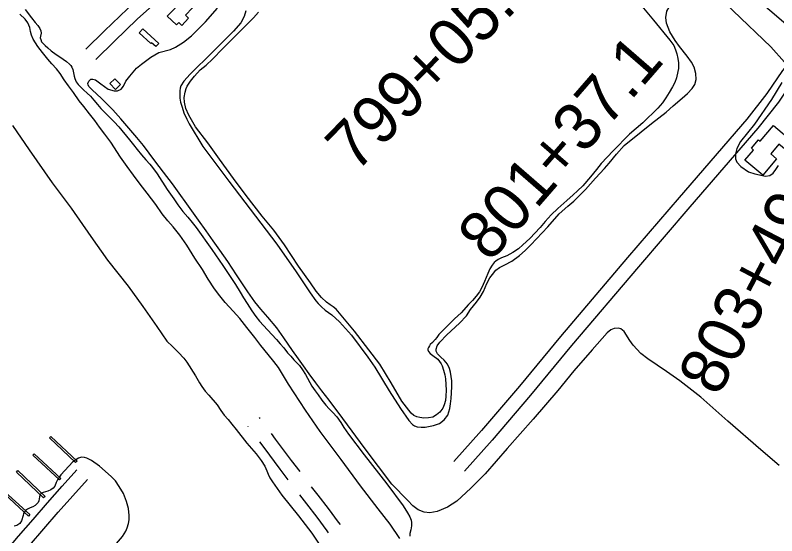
# Model space of a CAD drawing. Extents: x 3823584 to 3861785, y 301729 to 327625.
# Drawn here: x 3834881 to 3836481, y 323407 to 324501 of the extents above; entities that cross this region are included whole.
import ezdxf

# ---------------------------------------------------------------- set-up
doc = ezdxf.new("R2010")
doc.units = 0
for name, color, linetype in [('V-BLDG-OTLN', 7, 'Continuous'), ('V-CHAN-DOCK', 7, 'Continuous'), ('V-RIVR-EDGE', 7, 'Continuous'), ('V-ROAD-CNTR', 7, 'Continuous'), ('V-SITE-VEGE', 7, 'Continuous'), ('V-SURV-IDEN', 7, 'Continuous'), ('V-TOPO-SHOR', 7, 'Continuous')]:
    doc.layers.add(name, color=color, linetype=linetype)

msp = doc.modelspace()

# ---------------------------------------------------------------- linework, layer by layer
at = {"layer": 'V-BLDG-OTLN'}
for points in [[(3835200.4, 324499.1), (3835234.1, 324534.2), (3835242.5, 324526.1), (3835251.8, 324535.8), (3835256.1, 324531.6), (3835262.3, 324538), (3835268.6, 324532), (3835238.9, 324501.1), (3835245.4, 324494.8), (3835230.8, 324479.7), (3835224.6, 324485.7), (3835219.7, 324480.6)], [(3835148.9, 324472.4), (3835182.6, 324441.8), (3835176.4, 324435), (3835167.3, 324443.3), (3835166, 324441.9), (3835141.4, 324464.2)], [(3835090.5, 324367.6), (3835102.5, 324355.3), (3835092, 324345.2), (3835080.1, 324357.5)], [(3836474.5, 324269.6), (3836516.1, 324234.2), (3836501.5, 324217.1), (3836486, 324230.3), (3836468.6, 324209.8), (3836481.2, 324199.1), (3836451.9, 324164.8), (3836414.6, 324196.6), (3836432.7, 324217.7), (3836428, 324221.7), (3836442.9, 324239.2), (3836446.2, 324236.3)]]:
    msp.add_lwpolyline(points, close=True, dxfattribs=at)
at = {"layer": 'V-CHAN-DOCK'}
for points in [[(3835008, 323560.5), (3834952.9, 323612.4), (3834956.1, 323615.8), (3835011.2, 323563.9)], [(3834974.3, 323524.5), (3834918.1, 323576.3), (3834920.7, 323579.2), (3834976.9, 323527.4)], [(3834940.7, 323486.3), (3834883.6, 323540.7), (3834886.8, 323544), (3834943.9, 323489.6)], [(3834908.7, 323448.3), (3834848.4, 323503.1), (3834851.1, 323506.1), (3834911.4, 323451.2)]]:
    msp.add_lwpolyline(points, close=True, dxfattribs=at)
at = {"layer": 'V-RIVR-EDGE'}
msp.add_spline([(3836304.4, 325474.2), (3836346.4, 325438.3), (3836389.4, 325406.1), (3836417.6, 325385.4), (3836442.7, 325366.7), (3836470.2, 325340.9), (3836497.8, 325313.9), (3836554.9, 325258.4), (3836598.5, 325215.9), (3836636.4, 325181.1), (3836681.3, 325139.8), (3836737.1, 325093.4), (3836790.9, 325041.2), (3836840.3, 324993.5), (3836889.1, 324947.1), (3836934.6, 324907.1), (3836980.8, 324871), (3837015.5, 324849.1), (3837040.5, 324829.1), (3837085.4, 324787.2), (3837143.8, 324734.3), (3837181.6, 324700.8), (3837223.3, 324659.6), (3837272.1, 324619.6), (3837314.4, 324579.6), (3837346.4, 324546.8), (3837364.4, 324527.4), (3837395.8, 324500.4), (3837442, 324462.3), (3837492.7, 324423), (3837554.3, 324372.7), (3837573.6, 324361.1), (3837583.2, 324359.1), (3837596.7, 324352.6), (3837621.1, 324337.8), (3837648, 324319.7), (3837677.5, 324292), (3837718.6, 324249.5), (3837753.8, 324214.7), (3837781.4, 324188.9), (3837800, 324179.8), (3837820, 324170.8), (3837850.7, 324134.1), (3837874.4, 324110.2), (3837909.1, 324073.5), (3837941.8, 324040.6), (3837989.9, 323991.7), (3838022.6, 323960.7), (3838034.1, 323947.8), (3838046.3, 323933.7), (3838066.8, 323916.3), (3838089.9, 323892.4), (3838140.6, 323849.2), (3838186.1, 323811.2), (3838215.7, 323785.4), (3838265.7, 323736.4), (3838297.1, 323707.4), (3838336.9, 323671.9), (3838360, 323645.5), (3838385.6, 323627.5), (3838404.2, 323615.8), (3838421.6, 323601.7), (3838441.4, 323582.3), (3838460, 323567.5), (3838468.4, 323563.6), (3838484.4, 323555.2), (3838548.6, 323496.6), (3838595.4, 323464.3), (3838650, 323422.4), (3838701.3, 323379.8), (3838749.4, 323345.6), (3838798.2, 323317.9), (3838856.6, 323274.6), (3838933, 323221.7), (3838989.5, 323184.3), (3839037.6, 323150.1), (3839068.4, 323134.6), (3839093.4, 323105), (3839110.7, 323086.9), (3839122.9, 323081.1), (3839143.5, 323065.6), (3839172.3, 323044.4), (3839191, 323032.7), (3839216, 323016), (3839242.3, 323006.3), (3839316.8, 322969.4), (3839341.8, 322955.9), (3839371.4, 322944.2), (3839391.3, 322935.8), (3839417.6, 322920.3), (3839461.3, 322894.5), (3839483.7, 322873.2), (3839520.3, 322851.3), (3839555.6, 322828.7), (3839599.9, 322806.7), (3839718.7, 322751.1), (3839768.1, 322726.6), (3839807.9, 322705.9), (3839836.9, 322696.2), (3839865.1, 322680.7), (3839887.6, 322667.8), (3839924.2, 322652.3), (3839969.8, 322630.3), (3840004.4, 322612.2), (3840037.8, 322597.4), (3840085.4, 322579.9), (3840108.5, 322565.7), (3840121.9, 322548.9), (3840123.2, 322539.9), (3840122.5, 322533.5), (3840118, 322521.3), (3840112.8, 322514.2), (3840095.5, 322509.1), (3840089.7, 322509.2), (3840085.2, 322504.7), (3840084.5, 322498.2), (3840085.8, 322491.8), (3840130.7, 322467.3), (3840169.9, 322448.5), (3840197.5, 322439.5), (3840209.1, 322437.5), (3840231.6, 322441.3), (3840246.4, 322449), (3840266.3, 322458.6), (3840273.4, 322466.3), (3840278.6, 322471.4), (3840288.9, 322480.4), (3840296, 322484.9), (3840301.8, 322484.8), (3840308.2, 322484.8), (3840320.4, 322479), (3840324.9, 322470), (3840326.8, 322461.6), (3840338.3, 322450), (3840344.7, 322444.9), (3840366.6, 322437.7), (3840385.8, 322428.1), (3840421.8, 322409.3), (3840466.1, 322385.4), (3840492.4, 322368.7), (3840506.5, 322357), (3840533.5, 322340.3), (3840559.2, 322331.2), (3840587.4, 322322.1), (3840611.8, 322311.8), (3840642, 322296.3), (3840678.6, 322276.3), (3840712.6, 322255.6), (3840733.2, 322242.1), (3840784.5, 322210.4), (3840835.9, 322183.3), (3840892.4, 322153.6), (3840923.9, 322139.4), (3840950.8, 322127.1), (3840989.3, 322100), (3841017.6, 322082.6), (3841061.2, 322062.5), (3841092.7, 322044.4), (3841151.1, 322005.1), (3841210.8, 321964.4), (3841240.3, 321939.3), (3841300, 321894.8), (3841335.9, 321862.6), (3841374.4, 321823.9), (3841411.6, 321789.7), (3841444.9, 321758.1), (3841469.9, 321736.2), (3841482.1, 321724), (3841496.2, 321704.7), (3841509.1, 321694.3), (3841523.2, 321687.2), (3841573.9, 321660.7), (3841624, 321631.7), (3841667.6, 321606.5), (3841696.5, 321593.6), (3841738.3, 321575.5), (3841787.1, 321556.7), (3841816, 321552.1), (3841851.3, 321545), (3841886.7, 321533.3), (3841930.3, 321511.4), (3841950.2, 321498.5), (3841977.2, 321483), (3841998.4, 321476.5), (3842053, 321463.5), (3842082.5, 321456.3), (3842109.5, 321444.7), (3842146.1, 321427.3), (3842196.2, 321402.1), (3842241.1, 321374.9), (3842288.6, 321345.3), (3842321.4, 321327.2), (3842366.9, 321295.6), (3842395.2, 321280.1), (3842429.2, 321264.6), (3842452.4, 321258.7), (3842471, 321249.7)], degree=3, dxfattribs=at)
at = {"layer": 'V-ROAD-CNTR'}
for p, q in [((3835395.6, 323653.6), (3835394.5, 323655.1)), ((3835370.8, 323636.7), (3835370.5, 323637.1))]:
    msp.add_line(p, q, dxfattribs=at)
for points in [[(3835362.2, 325460.9), (3835509.5, 325334.3), (3835871.8, 325022.8), (3836108.4, 324817.6), (3836414, 324556.9), (3836839.8, 324193.7), (3837163.7, 323918.8), (3837445, 323669.4), (3837836.5, 323328.4), (3838069.6, 323134.9), (3838125.4, 323086.8), (3838256, 322989.5), (3838600, 322735.4), (3839019.3, 322425.4), (3839565.5, 322022.9), (3840024.9, 321675.2), (3840474.9, 321350), (3840728.4, 321161.3)], [(3835756.2, 325122.1), (3835727.3, 325085.6), (3835693.5, 325050.5), (3835646, 325004.3), (3835566.9, 324926.9), (3835457.9, 324826.8), (3835364.5, 324741.6), (3835267.6, 324652.3), (3835175, 324567.3), (3835116.6, 324514.7), (3835068.4, 324468.3), (3835029.1, 324429.5)], [(3835779, 325102.6), (3835749.9, 325065.8), (3835714.7, 325029.3), (3835667, 324982.8), (3835587.5, 324905.1), (3835478.1, 324804.6), (3835384.7, 324719.5), (3835287.9, 324630.2), (3835195.1, 324545.1), (3835137, 324492.7), (3835089.4, 324446.8), (3835050.1, 324408.2)], [(3836543.5, 324446.4), (3836522.3, 324418), (3836493.8, 324384.9), (3836460.6, 324336.3), (3836418.7, 324282.8), (3836276.1, 324118.1), (3836167.8, 323991.5), (3836027.2, 323826), (3835940.7, 323721.6), (3835861, 323627.8), (3835803, 323563)], [(3836540.6, 324442.5), (3836522.3, 324418), (3836493.8, 324384.9), (3836460.6, 324336.3), (3836418.7, 324282.8), (3836276.1, 324118.1), (3836167.8, 323991.5), (3836027.2, 323826), (3835940.7, 323721.6), (3835861, 323627.8), (3835803, 323563)], [(3836566.4, 324426.9), (3836545.8, 324399.2), (3836517.6, 324366.5), (3836484.8, 324318.6), (3836441.9, 324263.7), (3836298.9, 324098.5), (3836190.6, 323972.1), (3836050.2, 323806.7), (3835963.7, 323702.3), (3835883.6, 323608), (3835825.4, 323542.9)], [(3836564.7, 324424.6), (3836545.8, 324399.2), (3836517.6, 324366.5), (3836484.8, 324318.6), (3836441.9, 324263.7), (3836298.9, 324098.5), (3836190.6, 323972.1), (3836050.2, 323806.7), (3835963.7, 323702.3), (3835883.6, 323608), (3835825.4, 323542.9)], [(3835479.6, 323541.6), (3835461.8, 323565.1), (3835428.1, 323610.1), (3835419.5, 323621.6)], [(3835454.8, 323524.6), (3835437.9, 323547.1), (3835404.1, 323592.1), (3835394.8, 323604.6)], [(3834858.5, 323371.1), (3834888.1, 323405.9), (3834918.4, 323441.1), (3834948.9, 323476), (3834979.5, 323510.8), (3835010.4, 323545.4)], [(3834880.5, 323350.7), (3834910.9, 323386.4), (3834941.1, 323421.4), (3834971.4, 323456.3), (3835002, 323490.9), (3835032.8, 323525.4)], [(3835564.3, 323430.2), (3835560.6, 323435.2), (3835539.1, 323463.8), (3835517.4, 323492.2), (3835503.8, 323509.8)], [(3835539.6, 323413.2), (3835536.6, 323417.3), (3835515.2, 323445.7), (3835493.6, 323473.9), (3835479, 323492.8)]]:
    msp.add_lwpolyline(points, dxfattribs=at)
at = {"layer": 'V-SITE-VEGE'}
for points in [[(3836311.9, 324365.7), (3836311, 324378.7), (3836307.8, 324391.6), (3836302.5, 324402.2), (3836293.1, 324415), (3836276.8, 324435.2), (3836267.9, 324448.1), (3836256.9, 324466.1), (3836249.8, 324484.4), (3836248.2, 324496.6), (3836250.6, 324509.9), (3836259.9, 324526.5), (3836278.7, 324543.9), (3836295.7, 324552.5), (3836305.7, 324554.5), (3836319.8, 324556.1), (3836336.2, 324555.2), (3836350.5, 324549.6), (3836389.5, 324510.4), (3836468.9, 324434.4), (3836497.6, 324402.1)], [(3836172.7, 323817.3), (3836161, 323836.1), (3836154, 323841.9), (3836147.8, 323843.4), (3836139.5, 323842.7), (3836132.6, 323839.7), (3836125.1, 323833.7), (3836093.2, 323797.5), (3836055.2, 323753.2), (3836021.3, 323712), (3835969.3, 323652.2), (3835914.5, 323590.4), (3835868.4, 323537.2), (3835838.2, 323506.6), (3835809.4, 323479.8), (3835789.5, 323466.9), (3835768, 323458.1), (3835752, 323455), (3835740.4, 323456.3), (3835728.1, 323461.4), (3835716.7, 323469.4), (3835706.3, 323480.9), (3835672.5, 323515.4), (3835616.3, 323589.7), (3835569.4, 323653.5), (3835540.8, 323691.8), (3835525.4, 323711.6), (3835513, 323728.3), (3835498.7, 323747.1), (3835486.8, 323764.2), (3835476, 323778.9), (3835463.6, 323796.2), (3835445.6, 323822.6), (3835430.5, 323844.1), (3835412.2, 323866), (3835397.3, 323883.1), (3835384.7, 323898.7), (3835369.8, 323919.4), (3835346.2, 323955.5), (3835328.1, 323983.2), (3835311.2, 324007.3), (3835297, 324026.8), (3835282.6, 324048.1), (3835265.9, 324070.3), (3835241.5, 324104.4), (3835225.4, 324127.1), (3835211.3, 324146.5), (3835192.8, 324170.9), (3835174.5, 324194.9), (3835150.4, 324227.2), (3835136.9, 324244.2), (3835115.8, 324268.3), (3835103, 324283.2), (3835086, 324301.9), (3835062.3, 324326.3), (3835043, 324344), (3835035.5, 324351.2), (3835034.2, 324354.7), (3835033.8, 324357.6), (3835035.7, 324362.7), (3835040.1, 324366.4), (3835044.3, 324366.7), (3835049.5, 324365.2), (3835061, 324356.5), (3835076.5, 324345.7), (3835088.6, 324341.9), (3835096.1, 324341.9), (3835103.5, 324345.7), (3835108.3, 324351.7), (3835113.2, 324362.4), (3835121.5, 324373.1), (3835135.8, 324389.6), (3835146.2, 324398.3), (3835166.2, 324412.9), (3835182.9, 324422.6), (3835207.5, 324429.2), (3835218.1, 324433.6), (3835234.6, 324444.2), (3835251.1, 324458), (3835281.1, 324487.3), (3835306, 324515.9)], [(3835365.4, 324510.1), (3835361.9, 324498.4), (3835355.1, 324485.1), (3835339.6, 324467.4), (3835295.7, 324423.2), (3835248.8, 324377.1), (3835235.2, 324362.2), (3835229.2, 324352.6), (3835227.4, 324347.9), (3835226.9, 324341.9), (3835226.8, 324334.1), (3835227.1, 324326.9), (3835228.4, 324318.1), (3835231.5, 324307.7), (3835235.6, 324295.6), (3835241.4, 324282.6), (3835246.3, 324272.6), (3835275.1, 324225.3), (3835329.7, 324152.2), (3835430.9, 324019.7), (3835471.5, 323961.4), (3835489.7, 323934.6), (3835500.8, 323917.7), (3835512.7, 323900.6), (3835517.9, 323894.8), (3835524.5, 323888.1), (3835532.1, 323880.8), (3835546.1, 323871.2), (3835562.4, 323856.8), (3835587.7, 323828.5), (3835622, 323782.3), (3835636.4, 323761.1), (3835666.8, 323711.8), (3835690.5, 323674.3), (3835708.1, 323648.8), (3835715.7, 323640.8), (3835719.9, 323637.8), (3835726, 323635.7), (3835734.2, 323634.9), (3835742.2, 323635.4), (3835753, 323637), (3835759.9, 323638.6), (3835772.7, 323643), (3835782.5, 323650.2), (3835790, 323660.5), (3835794, 323674.6), (3835795.8, 323684.3), (3835797.4, 323695.3), (3835798.6, 323720.2), (3835798.5, 323732.2), (3835795.8, 323751), (3835793.6, 323758.6), (3835789.1, 323767.2), (3835782.5, 323775.6), (3835775.3, 323782.4), (3835768.4, 323789.3), (3835765.6, 323794.6), (3835765.5, 323799), (3835768, 323806.2), (3835773, 323813.6), (3835787.7, 323829.1), (3835814.8, 323853.9), (3835829.3, 323868.9), (3835837.8, 323882.2), (3835850.4, 323898.2), (3835857.8, 323908.2), (3835864.8, 323920.2), (3835872.3, 323937.4), (3835878.6, 323948.9), (3835883.7, 323956.3), (3835890.9, 323965), (3835899, 323971), (3835909.7, 323976.4), (3835924.5, 323984.2), (3835940.5, 323995.9), (3835952.4, 324006.8), (3835964.8, 324018.7), (3836000.3, 324056.2), (3836024.1, 324083.8), (3836042, 324099.8), (3836054.9, 324110.5), (3836070.2, 324125.5), (3836079.7, 324135), (3836100.7, 324158.4), (3836119.7, 324178.6), (3836129.5, 324190.4), (3836144.4, 324209.1), (3836160.5, 324227.1), (3836196.2, 324256.2), (3836218.1, 324273.2), (3836233.6, 324285.6), (3836249, 324297.5), (3836263.6, 324310.7), (3836282.9, 324327), (3836293.6, 324336.4), (3836303.9, 324346.9), (3836309.1, 324355.2), (3836311.9, 324365.7)], [(3836492.2, 324359.5), (3836470.3, 324323.7), (3836434.4, 324272.4), (3836404.9, 324235.8), (3836397.7, 324220.7), (3836394.6, 324209.7), (3836394.6, 324199.4), (3836397.8, 324191.9), (3836405.8, 324182.9), (3836422, 324172), (3836435.1, 324167.8), (3836457.7, 324162.6), (3836467, 324164.4), (3836473.8, 324168.9), (3836479.6, 324176.8), (3836485, 324184.9)], [(3836486.5, 323554.6), (3836447.8, 323587.2), (3836378.8, 323647.9), (3836321.6, 323698.2), (3836277.4, 323732.5), (3836250, 323752.1), (3836210.7, 323778.9), (3836196, 323790.2), (3836179.6, 323807.4), (3836172.7, 323817.3)]]:
    msp.add_lwpolyline(points, dxfattribs=at)
at = {"layer": 'V-TOPO-SHOR'}
for points in [[(3836194, 324524.2), (3836222.1, 324490.5), (3836257, 324448.5), (3836264.9, 324437.1), (3836268.7, 324428.2), (3836271.7, 324419.6), (3836273.7, 324410.2), (3836274.8, 324400.8), (3836274.6, 324389.4), (3836273.7, 324382.5), (3836270.5, 324369.8), (3836267.1, 324359.9), (3836262.2, 324350.3), (3836255.6, 324338.5), (3836248.4, 324327.2), (3836241.2, 324316.7), (3836231.8, 324305.4), (3836199.7, 324274.9), (3836172, 324250.8), (3836137.5, 324216.1), (3836112.7, 324189.5), (3836102.7, 324176.9), (3836090, 324161.6), (3836073.8, 324142.7), (3836062.7, 324132.2), (3836053.6, 324123.5), (3836040, 324111.4), (3836021.4, 324094.5), (3836007.2, 324081.2), (3835994.8, 324067.3), (3835984.3, 324054.7), (3835962.5, 324031.6), (3835947.5, 324018.3), (3835938.5, 324010.3), (3835926.9, 324002.2), (3835914.2, 323995.4), (3835902.8, 323991.1), (3835895.9, 323987.9), (3835891, 323984.3), (3835887.4, 323981), (3835883, 323975.6), (3835878.6, 323968), (3835874.4, 323958.3), (3835867, 323941.4), (3835861.6, 323928.9), (3835856.5, 323919.8), (3835849.6, 323910.4), (3835841.8, 323901.3), (3835833.8, 323892.7), (3835818.4, 323875.5), (3835804, 323863), (3835790.3, 323849.1), (3835778.8, 323837.7), (3835771.5, 323829.8), (3835767.2, 323823.9), (3835763.5, 323819.3), (3835757.6, 323812.9), (3835753.3, 323808.6), (3835751.3, 323806.1), (3835749.3, 323802.9), (3835748.2, 323799.5), (3835748.4, 323797.4), (3835749.7, 323794), (3835753, 323789.7), (3835758.3, 323786)], [(3835158.6, 324127.2), (3835143.6, 324145.6), (3835129.7, 324165.1), (3835116.2, 324183.4), (3835102.1, 324202.7), (3835081.7, 324234.2), (3835069.4, 324250.8), (3835058.1, 324266), (3835048.1, 324280.1), (3835037, 324294), (3835024.9, 324308.9), (3835015.6, 324320.9), (3835003.4, 324338.3), (3834992.6, 324352.4), (3834984, 324365.1), (3834975.5, 324378.5), (3834967.7, 324388.6), (3834958.1, 324399), (3834949.5, 324408.4), (3834938, 324422.8), (3834928.4, 324435.4), (3834918.7, 324450.4), (3834915.4, 324458.8), (3834913.4, 324467), (3834911.5, 324475.5), (3834907.5, 324484.8), (3834901.6, 324492.7), (3834891, 324503)], [(3834902, 324512.9), (3834915.5, 324495.3), (3834922.9, 324485.9), (3834928.4, 324479.3), (3834932.6, 324473.2), (3834935, 324468.4), (3834935.4, 324463.6), (3834934, 324457.3), (3834933.7, 324453.8), (3834934.5, 324450.2), (3834936.5, 324445.2), (3834938.4, 324443.1), (3834943.9, 324437.3), (3834949.5, 324432.2), (3834956.4, 324426.3), (3834967, 324418.2), (3834974.7, 324413.3), (3834981.9, 324408.7), (3834988.9, 324403.8), (3834995.1, 324398.5), (3834998.1, 324395.2), (3835000.3, 324391.9), (3835002.1, 324387.3), (3835003.5, 324379.8), (3835004.6, 324372.9), (3835006, 324367.7), (3835009.2, 324360.7), (3835013.3, 324355.4), (3835024.7, 324344.4), (3835032.2, 324337.4), (3835038.9, 324330.8), (3835046.2, 324322.6), (3835054.2, 324313.2), (3835061.1, 324305.3), (3835067.6, 324298.1), (3835073.6, 324292.2), (3835081.6, 324284.1), (3835088.6, 324276.9), (3835098.7, 324266.3), (3835121.3, 324239.3), (3835129.8, 324228.4), (3835137, 324218.5), (3835146.7, 324207.3), (3835155.8, 324197), (3835164, 324188), (3835169.7, 324180.8), (3835179, 324167.4), (3835200.4, 324134.9), (3835214.1, 324115.2), (3835222.7, 324102.3), (3835233.5, 324088.4), (3835243.6, 324076.5), (3835252.8, 324065.1), (3835261, 324054.7), (3835293.9, 324008.9), (3835317.6, 323975), (3835344, 323935.2), (3835353.6, 323919.2), (3835360.7, 323906.7), (3835368.1, 323894.9), (3835378.3, 323879.4), (3835386.7, 323868), (3835394.3, 323857.6), (3835402.5, 323848.7)], [(3835476.5, 323973.2), (3835446.8, 324018.1), (3835424.3, 324049.1), (3835400.2, 324078.9), (3835366.4, 324121.8), (3835339.5, 324157.6), (3835310.3, 324198.8), (3835285.6, 324232.5), (3835259.7, 324266.5), (3835245.5, 324290.7), (3835239.6, 324305.3), (3835236.8, 324318.2), (3835236.3, 324328.1), (3835238.1, 324339.5), (3835240.5, 324346.8), (3835242.4, 324351.7), (3835249.2, 324362.3), (3835257.6, 324373.1), (3835270, 324386.5), (3835282, 324396.3), (3835295.9, 324409), (3835317.6, 324431.1), (3835335.6, 324449.5), (3835348.9, 324462.8), (3835363.7, 324477.5), (3835381.5, 324495.4), (3835392, 324507.4)], [(3834875.3, 324269.2), (3834910.5, 324218), (3834958.9, 324148.8), (3834998.5, 324095.7), (3835039.7, 324036.2), (3835075, 323986.5), (3835118.6, 323931.5), (3835149.3, 323888.5), (3835178.5, 323846.5), (3835199.7, 323816), (3835211.4, 323804.8), (3835224.4, 323792.2), (3835235.3, 323780.1), (3835241.5, 323771.5), (3835259.8, 323742.7), (3835268.2, 323728.1), (3835273, 323720.4), (3835279.9, 323711.1), (3835287.6, 323702.3), (3835305.3, 323681.8), (3835313.4, 323670.4), (3835320.4, 323660.6), (3835328.2, 323650.9), (3835336.2, 323641.4), (3835345.1, 323629.9), (3835367.7, 323601.5), (3835387.4, 323579.1), (3835398.1, 323565.3), (3835405.6, 323553), (3835409.5, 323543.5), (3835412.4, 323536.3), (3835416.2, 323528.9), (3835421.6, 323520), (3835441.4, 323492.1)], [(3835689.5, 323401.2), (3835668.8, 323431.1), (3835643.4, 323463.4), (3835606.9, 323511.7), (3835566.3, 323567.1), (3835521.8, 323626.1), (3835491, 323670.6), (3835455, 323725.6), (3835434.1, 323760.5), (3835424.4, 323773.3), (3835412.8, 323788), (3835397.3, 323806.7), (3835384.3, 323823.8), (3835367.7, 323844.5), (3835352.7, 323863.5), (3835339.2, 323879.1), (3835322.2, 323897), (3835310.9, 323911.1), (3835300, 323926.1), (3835286.7, 323945.9), (3835274.4, 323966.3), (3835258.6, 323990.4), (3835241.7, 324017.8), (3835226.7, 324038.4), (3835213, 324056), (3835201.7, 324069.1), (3835190, 324083.8), (3835176.7, 324102.9), (3835158.6, 324127.2)], [(3835758.3, 323786), (3835769.3, 323778), (3835772.9, 323773.1), (3835775.9, 323768.4), (3835777.9, 323763.8), (3835781.2, 323755.2), (3835783.5, 323745), (3835785, 323736.7), (3835786.2, 323725), (3835786.6, 323713.2), (3835785.9, 323700.1), (3835784.9, 323691.3), (3835782.3, 323682.1), (3835779.3, 323674.8), (3835773.2, 323666.4), (3835766.4, 323660.7), (3835758.3, 323656.3), (3835749.2, 323654.5), (3835739.6, 323654.2), (3835731, 323655.4), (3835725, 323656.9), (3835718.4, 323659.9), (3835713.4, 323664.3), (3835693.7, 323689.7), (3835671.1, 323728.3), (3835647.5, 323767.8), (3835624.3, 323797.9), (3835594.2, 323836.6), (3835566.3, 323870.6), (3835555.8, 323883.3), (3835549.5, 323888.2), (3835542.6, 323892.5), (3835534.9, 323897.8), (3835524.5, 323907.6), (3835513.6, 323921.3), (3835501.5, 323938.5), (3835476.5, 323973.2)], [(3835402.5, 323848.7), (3835420.6, 323829.7), (3835429.9, 323819.4), (3835437.9, 323810.2), (3835445.3, 323801.6), (3835453.4, 323791.7), (3835460, 323784.2), (3835466.8, 323776.8), (3835472.4, 323771.2), (3835478.4, 323764.4), (3835484.8, 323755.4), (3835490.7, 323745.7), (3835504.4, 323721.6), (3835511.3, 323711.6), (3835517.9, 323702.8), (3835525.5, 323691.8), (3835533.6, 323681.6), (3835540.8, 323673.8), (3835548.3, 323666.1), (3835556.6, 323656.9), (3835565, 323645.2), (3835571.8, 323634.2), (3835581.6, 323620.1), (3835614.5, 323577.2), (3835661.8, 323515.7), (3835696.1, 323469.8), (3835705.3, 323455), (3835710.1, 323446.7), (3835713, 323439.4), (3835713.5, 323434.5), (3835713.6, 323427.4), (3835712.4, 323419.2), (3835710.1, 323411.8), (3835710, 323406.2)], [(3835091.4, 323522.3), (3835082.7, 323531.6), (3835057.9, 323553.4), (3835041, 323565), (3835031.7, 323569.9), (3835026.3, 323571.6), (3835020.5, 323571.9), (3835013.7, 323569.8), (3835002.4, 323562.3), (3834976.9, 323535.1)], [(3834976.9, 323535.1), (3834969.8, 323524.7), (3834966.8, 323518.7), (3834963.9, 323511.4), (3834960.9, 323506.7), (3834955.9, 323503.2), (3834949.4, 323500.6), (3834939.9, 323497.8), (3834936.2, 323496.2), (3834933.7, 323493.7), (3834931.9, 323488.8), (3834930.3, 323480.5), (3834928.9, 323477), (3834926.4, 323473.8), (3834922.9, 323470.6), (3834917.8, 323467.7), (3834912.5, 323465.3), (3834906.6, 323463), (3834902.6, 323459.7), (3834898.5, 323453.6), (3834897.6, 323449.7), (3834894.4, 323437.9), (3834890.4, 323432.4), (3834884.5, 323428.2), (3834878.5, 323427)], [(3834841.6, 323100), (3834901.6, 323170.7), (3834967.2, 323245.2), (3835031.2, 323318.3), (3835085.1, 323380.7), (3835106.5, 323405.3), (3835113.3, 323416.4), (3835116.2, 323423.6), (3835119.1, 323432.6), (3835120.5, 323440), (3835120.5, 323449.7), (3835118.8, 323464.1), (3835115.1, 323478.5), (3835108.4, 323495.5), (3835099.6, 323510.2), (3835091.4, 323522.3)], [(3835441.4, 323492.1), (3835476.4, 323449), (3835504.3, 323412.6), (3835518.1, 323391.3)]]:
    msp.add_lwpolyline(points, dxfattribs=at)

# ---------------------------------------------------------------- texts
at = {"layer": 'V-SURV-IDEN'}
for s, rotation, p in [('799+05.0', 45.4575, (3835596.2, 324168.1)), ('801+37.1', 49.0456, (3835878.7, 323979.5)), ('803+49.2', 62.4229, (3836358.4, 323697.1))]:
    msp.add_text(s, height=100, rotation=rotation, dxfattribs=at).set_placement(p)

doc.saveas('drawing.dxf')
